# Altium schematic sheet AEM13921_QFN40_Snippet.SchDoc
size A4; DocumentNumber: 1; SheetNumber: 1; SheetTotal: 1; Organization: e-peas S.A.; Address1_Global: Bd Baudouin 1er N°19; Address2_Global: 1348 Ottignies-Louvain-La-Neuve; Address3_Global: Belgium; Name: AEM13920 QFN40 Snippet
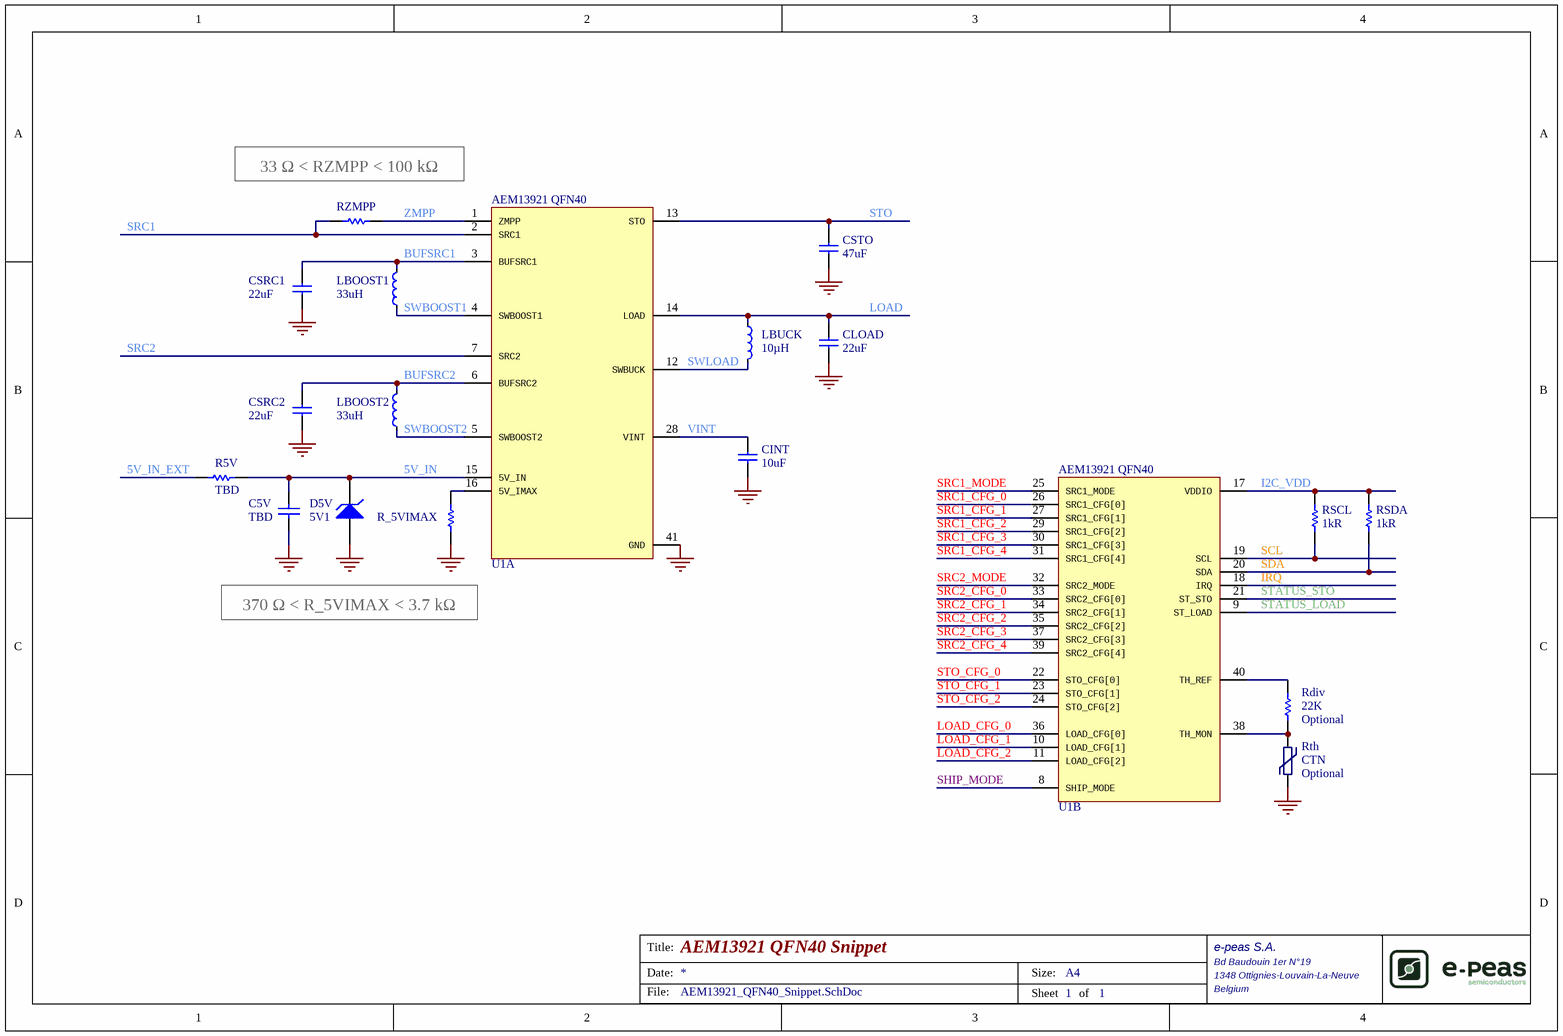
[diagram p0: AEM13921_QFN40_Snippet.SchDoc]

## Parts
C5V  value TBD  [0603_[1608]]  (hidden comment: Cap Ceramic 0603 TBD)
CINT  10uF  [0402_[1005]]
CLOAD  22uF  [0603_[1608]]
CSRC1  22uF  [0603_[1608]]
CSRC2  22uF  [0603_[1608]]
CSTO  47uF  [0603_[1608]]
D5V  5V1  [SOT23-3P  3x1.40mm Pitch=0.915mm diode AK]
LBOOST1  33uH  [Coilcraft-LPS4018]
LBOOST2  33uH  [Coilcraft-LPS4018]
LBUCK  10µH  [inductor_2520]
R5V  TBD  [Resistor_0603_[1608]]
R_5VIMAX  TBD  [Resistor_0603_[1608]]  (value not drawn)
Rdiv  22K  [Resistor_0402]
RSCL  1kR  [Resistor_0603_[1608]]
RSDA  1kR  [Resistor_0603_[1608]]
Rth  CTN  [Axial-SMD0603-0402 - 1608M]
RZMPP  TBD  [Resistor_0603_[1608]]  (value not drawn)
U1  AEM13921_QFN40  [QFN40_5x5mm_pitch0.4mm_ASE_98A0040QN185]  (value not drawn)  (parts A,B of 2)

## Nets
GND: C5V.1 CINT.1 CLOAD.1 CSRC1.1 CSRC2.1 CSTO.1 D5V.A R_5VIMAX.1 Rth.1 U1.41(GND)
5V_IN: C5V.2 D5V.K R5V.2 U1.15(5V_IN)
5V_IN_EXT: R5V.1
BUFSRC1: CSRC1.2 LBOOST1.1 U1.3(BUFSRC1)
BUFSRC2: CSRC2.2 LBOOST2.2 U1.6(BUFSRC2)
I2C_VDD: RSCL.2 RSDA.2 U1.17(VDDIO)
IRQ: U1.18(IRQ)
LOAD: CLOAD.2 LBUCK.1 U1.14(LOAD)
LOAD_CFG_0: U1.36(LOAD_CFG[0])
LOAD_CFG_1: U1.10(LOAD_CFG[1])
LOAD_CFG_2: U1.11(LOAD_CFG[2])
SCL: RSCL.1 U1.19(SCL)
SDA: RSDA.1 U1.20(SDA)
SHIP_MODE: U1.8(SHIP_MODE)
SRC1: RZMPP.1 U1.2(SRC1)
SRC1_CFG_0: U1.26(SRC1_CFG[0])
SRC1_CFG_1: U1.27(SRC1_CFG[1])
SRC1_CFG_2: U1.29(SRC1_CFG[2])
SRC1_CFG_3: U1.30(SRC1_CFG[3])
SRC1_CFG_4: U1.31(SRC1_CFG[4])
SRC1_MODE: U1.25(SRC1_MODE)
SRC2: U1.7(SRC2)
SRC2_CFG_0: U1.33(SRC2_CFG[0])
SRC2_CFG_1: U1.34(SRC2_CFG[1])
SRC2_CFG_2: U1.35(SRC2_CFG[2])
SRC2_CFG_3: U1.37(SRC2_CFG[3])
SRC2_CFG_4: U1.39(SRC2_CFG[4])
SRC2_MODE: U1.32(SRC2_MODE)
STATUS_LOAD: U1.9(ST_LOAD)
STATUS_STO: U1.21(ST_STO)
STO: CSTO.2 U1.13(STO)
STO_CFG_0: U1.22(STO_CFG[0])
STO_CFG_1: U1.23(STO_CFG[1])
STO_CFG_2: U1.24(STO_CFG[2])
SWBOOST1: LBOOST1.2 U1.4(SWBOOST1)
SWBOOST2: LBOOST2.1 U1.5(SWBOOST2)
SWLOAD: LBUCK.2 U1.12(SWBUCK)
VINT: CINT.2 U1.28(VINT)
ZMPP: RZMPP.2 U1.1(ZMPP)
NetR_5VIMAX_2: R_5VIMAX.2 U1.16(5V_IMAX)
NetRdiv_1: Rdiv.1 Rth.2 U1.38(TH_MON)
NetRdiv_2: Rdiv.2 U1.40(TH_REF)

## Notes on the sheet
- 33 Ω < RZMPP < 100 kΩ
- 370 Ω < R_5VIMAX < 3.7 kΩ
- (near Rdiv) Optional
- (near Rth) Optional
- Title:
- Date:
- AEM13921 QFN40 Snippet
- Size:
- A4
- File:
- Sheet
- of

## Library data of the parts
C5V = Cap Ceramic 0603 TBD: Package Metric: 1608
CINT = Cap Ceramic 10uF, 6.3V, 20%, X5R, 0402: Manuf: MURATA; Manuf PN: GRM155R60J106ME44D; Package Metric: 1005
CLOAD CSRC1 CSRC2 = Cap Ceramic 22uF, 10V, 20%, X5R 0603: Manuf: MuRata; Manuf PN: GRM188R61A226ME15D; Package Metric: 1608
CSTO = Cap Ceramic 47uF 6.3V +/-20% X5R 0603: Manuf: Murata; Manuf PN: GRM188R60J476ME15D; Package Metric: 1608
D5V = Zener 5.1V 350mW BZX84C5V1-TP: Zener Diode 5.1 V 350 mW ±5% Surface Mount SOT-23; Manuf: Micro Commercial Co; Vbr: 5.1V; I continous: 68mA
LBOOST1 LBOOST2 = Power Inductor 33uH - 0,68A - LPS4018 - Small Symbol: Power Inductor 33uH - 0,68A - LPS4018; Manuf: Coilcraft; Manuf PN: LPS4018-333MRB; Tol: 20%; Rdc: 420mOhms; Self Resonant Frequency: 20MHz; Max DC Current: 800mA
LBUCK = Power Inductor 10µF TDK VLS-CX-1: Manuf PN: VLS252012CX-100M-1; Tol: ±20%; Rdc: 0.482 ohm; Max DC Current: 970 mA
R5V R_5VIMAX RZMPP = Resistor TBD - 0603: Mnt: SMD
Rdiv = Resistor 22KR - 0402 - 50V: Manuf: Yageo; Manuf PN: RC0402FR-0722KL; P max mW: 63; Tol %: 1%; Mnt: SMD
RSCL RSDA = Resistor 1kOhm - 0603 - 75V - 1%: Manuf: Multicomp; Manuf PN: MCWR06X1001FTL; P max mW: 100; Tol %: 1; V max: 75V; Mnt: SMD; Package Metric: 1608
Rth = Thermistor 10kR CTN Double Footprint (SMD 0603+0402+THT): Manuf: Murata; Manuf PN: NCP15XH103J03RC; P max mW: 0402; Mnt: SMD; Value: 10kR
U1 = AEM13921 QFN40: Manuf: e-peas; Manuf PN: 10AEM13921J0000; Mnt: SMD; Pitch: 0.4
